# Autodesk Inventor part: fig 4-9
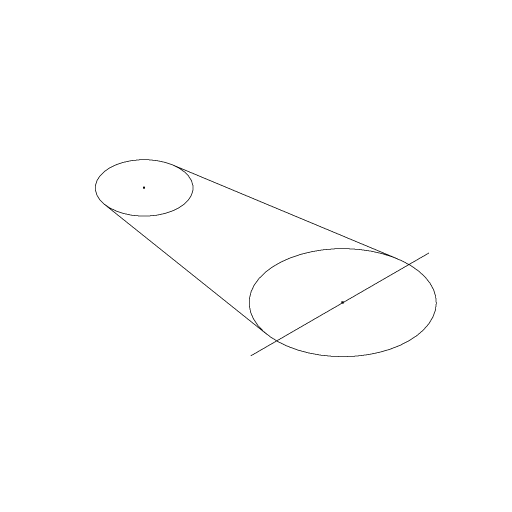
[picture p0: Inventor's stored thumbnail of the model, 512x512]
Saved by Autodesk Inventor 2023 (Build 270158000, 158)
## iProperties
Created: 2005-02
Part Number: fig 4-9
Document SubType Name: Modeling
Designer: CADCIM
Manufacturer: Standard
Standards Organization: Custom
Density: 1 g/cm^3
Material: Generic
Appearance: Default
Author: CADCIM
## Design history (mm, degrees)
sketch "Sketch1"
  geometry: L1 (-28.496, 15.735)-(10.446, 21.986); L2 (-28.503, 2.004)-(10.432, -4.291); L3 (12.58, 26.117)-(12.58, -9.642); A1 r 6.954 centre (-27.393, 8.869) between (-28.496, 15.735) and (-28.503, 2.004); A2 r 13.308 centre (12.555, 8.846) between (10.446, 21.986) and (10.432, -4.291)
  constraints: 6 end point, 4 point on circle, 4 tangent, 2 centre point, 1 vertical, 1 other
